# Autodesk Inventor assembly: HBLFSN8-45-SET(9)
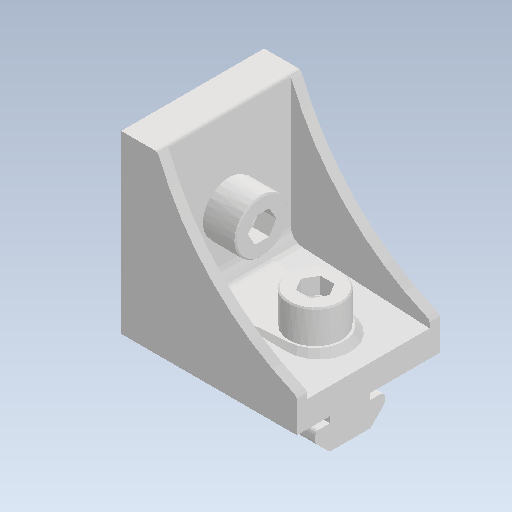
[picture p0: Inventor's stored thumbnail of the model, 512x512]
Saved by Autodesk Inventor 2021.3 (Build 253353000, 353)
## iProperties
Created: 2022-02
Part Number: HBLFSN8-45-SET(9)
Document SubType Name: Assembly
Designer: kengo
Author: kengo
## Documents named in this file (4)
- C:\Users\kengo\Documents\S2S_frame\SDC345\frame_misumi_ver12\HBLFSN8-45-SET(9).iam
- C:\Users\kengo\Documents\S2S_frame\SDC345\frame_misumi_ver12\HBLFSN8-45.ipt
- C:\Users\kengo\Documents\S2S_frame\SDC345\frame_misumi_ver12\HNTT8-8.ipt
- C:\Users\kengo\Documents\S2S_frame\SDC345\frame_misumi_ver12\CBM8-20.ipt
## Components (5 placed, 3 different names)
1. HBLFSN8-45
2. HNTT8-8
3. CBM8-20
4. HNTT8-8:1
5. CBM8-20:1
